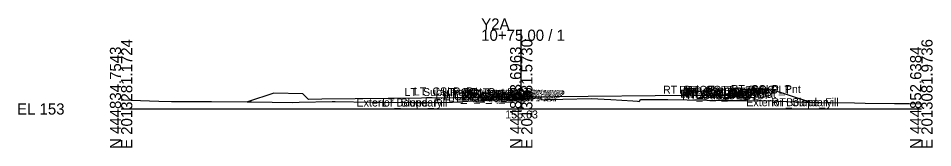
# Model space of a CAD drawing. Extents: x -26 to 203, y -10 to 5517.
# Drawn here: x -25.7 to 202.8, y 1490.3 to 1522.7 of the extents above; entities that cross this region are included whole.
import ezdxf

# ---------------------------------------------------------------- set-up
doc = ezdxf.new("R2010")
doc.units = 0
for name, color, linetype in [('Default', 7, 'Continuous'), ('Exist Cross Section Cell', 7, 'Continuous'), ('Exist XS Center Line Elevation Label', 7, 'Continuous'), ('Exist XS Ground Line', 7, 'Continuous'), ('Prop XS Earthwork Shape', 7, 'Continuous'), ('Scratch_Level_0', 7, 'Continuous')]:
    doc.layers.add(name, color=color, linetype=linetype)

msp = doc.modelspace()

# ---------------------------------------------------------------- linework, layer by layer
at = {"layer": 'Exist Cross Section Cell'}
for p, q in [((100, 1500), (100, 1519.85)), ((0, 1500), (100, 1500)), ((100, 1500), (200, 1500))]:
    msp.add_line(p, q, dxfattribs=at)
at = {"layer": 'Exist XS Ground Line'}
msp.add_lwpolyline([(0, 1502.27), (2.52, 1502.23), (9.41, 1501.98), (12.56, 1501.89), (20.44, 1501.85), (22.6, 1501.87), (31.48, 1501.77), (32.64, 1501.75), (42.83, 1501.65), (44.49, 1501.69), (52.73, 1501.85), (53.54, 1501.86), (62.77, 1501.71), (64.57, 1501.68), (72.81, 1501.58), (75.6, 1501.63), (82.85, 1501.68), (86.64, 1501.92), (92.89, 1502.29), (99.21, 1502.6), (100, 1502.63), (104.77, 1502.8), (105.19, 1502.3), (105.88, 1502.34), (106.79, 1502.4), (110.36, 1502.47), (117.49, 1502.65), (122.38, 1502.34), (127.86, 1502.01), (129.03, 1501.93), (129.45, 1501.91), (129.87, 1502.41), (133.85, 1502.41), (134.89, 1502.41), (136.66, 1502.41), (151.18, 1502.15), (153.14, 1502.12), (156.33, 1502.09), (163.18, 1502.01), (163.86, 1501.99), (173.22, 1501.65), (174.89, 1501.62), (183.27, 1501.52), (185.92, 1501.47), (193.31, 1501.37), (196.95, 1501.35), (200, 1501.31)], dxfattribs=at)
at = {"layer": 'Prop XS Earthwork Shape'}
msp.add_lwpolyline([(100, 1502.93), (50.14, 1502.43), (46.8, 1502.4), (45.41, 1503.79), (38.14, 1503.94), (31.62, 1501.77), (32.64, 1501.75), (42.83, 1501.65), (44.49, 1501.69), (52.73, 1501.85), (53.54, 1501.86), (62.77, 1501.71), (64.57, 1501.68), (72.81, 1501.58), (75.6, 1501.63), (82.85, 1501.68), (86.64, 1501.92), (92.89, 1502.29), (99.21, 1502.6), (100, 1502.63), (104.77, 1502.8), (105.19, 1502.3), (105.88, 1502.34), (106.79, 1502.4), (110.36, 1502.47), (117.49, 1502.65), (122.38, 1502.34), (127.86, 1502.01), (129.03, 1501.93), (129.45, 1501.91), (129.87, 1502.41), (133.85, 1502.41), (134.89, 1502.41), (136.66, 1502.41), (151.18, 1502.15), (153.14, 1502.12), (156.33, 1502.09), (163.18, 1502.01), (163.86, 1501.99), (172.09, 1501.69), (162.22, 1504.98), (154.91, 1504.83), (153.55, 1503.46), (150.22, 1503.43)], close=True, dxfattribs=at)

# ---------------------------------------------------------------- texts
at = {"layer": 'Default'}
msp.add_text('-', height=0.0001, dxfattribs=at).set_placement((0, 1500))
at = {"layer": 'Exist Cross Section Cell'}
for s, p in [('Y2A', (90, 1519.85)), ('10+75.00 / 1', (90, 1517.05)), ('EL 153', (-26, 1498.6))]:
    msp.add_text(s, height=2.8, dxfattribs=at).set_placement(p)
for s, p in [('N 444834.7543', (0, 1490)), ('E 2013281.1724', (2.8, 1490)), ('N 444843.6963', (100, 1490)), ('E 2013181.5730', (102.8, 1490)), ('N 444852.6384', (200, 1490)), ('E 2013081.9736', (202.8, 1490))]:
    msp.add_text(s, height=2.8, rotation=90, dxfattribs=at).set_placement(p)
at = {"layer": 'Exist XS Center Line Elevation Label'}
msp.add_text('155.63', height=2, dxfattribs=at).set_placement((95.99, 1497.63))
at = {"layer": 'Scratch_Level_0'}
for s, p in [('LT_Sub_Trench_Out_DLT', (70.84, 1503.24)), ('LT_CSLP_Pnt', (73.17, 1503.39)), ('LT_CG1_Shelf_Out', (78.55, 1502.18)), ('LT_CG_Top_Face', (80.26, 1503.2)), ('LT_CG_Top_BOC', (80.78, 1503.2)), ('LT_CG_Bot_BOC', (80.81, 1502.19)), ('LT_CG_Top_Gut', (81.24, 1502.7)), ('LT_Sub_OEOP', (81.77, 1501.85)), ('LT_CG_Bot_IE', (84.91, 1502.21)), ('LT_Sub_OEOT', (85.08, 1501.88)), ('LT_PV2_OEOT', (85.17, 1502.55)), ('LT_PV3_OEOT', (85.17, 1502.21)), ('LT_PV1_OEOT', (85.74, 1502.8)), ('RT_Sub_OEEOP', (89.17, 1501.93)), ('LT_Sub_OEEOP', (89.21, 1501.93)), ('RT_PV2_OEEOP', (89.26, 1502.6)), ('RT_PV3_OEEOP', (89.26, 1502.26)), ('LT_PV2_OEEOP', (89.31, 1502.6)), ('LT_PV3_OEEOP', (89.31, 1502.26)), ('RT_PV1_OEEOP', (89.83, 1502.72)), ('LT_PV1_OEEOP', (89.87, 1502.72)), ('RT_PV2_IEEOP', (89.91, 1502.6)), ('LT_PV2_IEEOP', (89.95, 1502.6)), ('RT_PV1_IEEOP', (90.47, 1502.72)), ('LT_PV1_IEEOP', (90.52, 1502.72)), ('PV2_PGL', (93.91, 1502.6)), ('PV1_PGL', (94.47, 1502.85)), ('RT_Sub_Trench_Out_DLT', (135.43, 1503.83)), ('RT_CG_Top_Face', (139.43, 1503.79)), ('RT_CG1_Shelf_Out', (139.72, 1502.79)), ('RT_CG_Bot_IE', (140.08, 1502.76)), ('RT_Sub_OEOT', (140.25, 1502.43)), ('RT_PV2_OEOT', (140.34, 1503.1)), ('RT_PV3_OEOT', (140.34, 1502.76)), ('RT_CG_Top_Gut', (140.41, 1503.29)), ('RT_PV1_OEOT', (140.91, 1503.35)), ('RT_CG_Top_BOC', (140.95, 1503.79)), ('RT_CG_Bot_BOC', (140.98, 1502.79)), ('RT_Sub_OEOP', (143.61, 1502.46)), ('RT_CSLP_Pnt', (152.34, 1503.98)), ('Exterior Boundary', (58.83, 1500.62)), ('LT_Slope_Fill', (65.21, 1500.62)), ('Exterior Boundary', (156.23, 1500.69)), ('RT_Slope_Fill', (162.56, 1500.69))]:
    msp.add_text(s, height=2, dxfattribs=at).set_placement(p)

doc.saveas('drawing.dxf')
